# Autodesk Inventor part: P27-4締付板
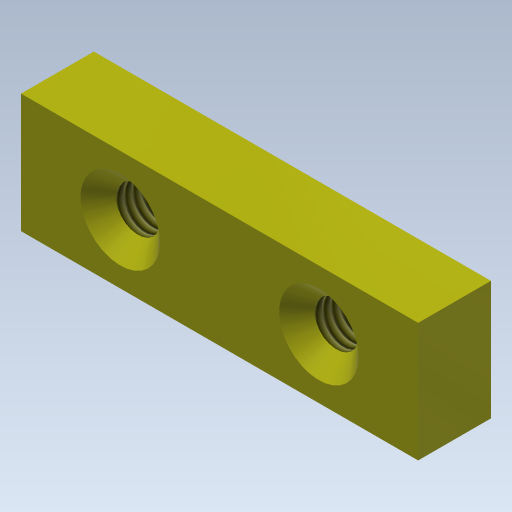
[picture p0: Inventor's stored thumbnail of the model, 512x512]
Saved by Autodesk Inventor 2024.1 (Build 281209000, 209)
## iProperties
Created: 2008-07
Part Number: P27-4締付板
Document SubType Name: Modeling
Designer: y-shimohigashi
Density: 1 g/cm^3
Stock Number: P24-4締付板
Material: 一般
Appearance: 黄
Author: y-shimohigashi
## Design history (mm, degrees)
sketch "スケッチ1"
  geometry: L1 (-30, 5.5)-(30, 5.5); L2 (30, 5.5)-(30, -5.5); L3 (30, -5.5)-(-30, -5.5); L4 (-30, -5.5)-(-30, 5.5); L5 (30, 5.5)-(-30, -5.5); 2 further points
  constraints: 10 end point, 2 parallel, 1 coincident, 1 horizontal, 1 midpoint, 1 perpendicular
  dimensions: "d0" = 11 distance of L1.end L2.end; "d1" = 60 distance of L2.end L3.end
extrude "押し出し1" new body sketch "スケッチ1" distance "d2" = 18; taper "d3" = 0 deg
sketch "スケッチ2"
  geometry: L1 (30, -3.6)-(30, 21.6) reference; L2 (60, 0)-(60, 18) reference; 3 further points
  constraints: 1 horizontal alignment, 1 midpoint, 1 symmetric about line
  dimensions: "d4" = 30 distance of point (45, 9) point (15, 9)
hole "穴1" sketch "スケッチ2" diameter "d5" = 6.647; stored, may be unused: countersink angle "d9" = 90 deg, drill point angle "d11" = 118 deg; dims "d6" = 6, "d7" = 12, "d8" = 2, "d10" = 8
node "ソリッド1"
node "ソリッド ボディ"
node "サーフェス ボディ"
